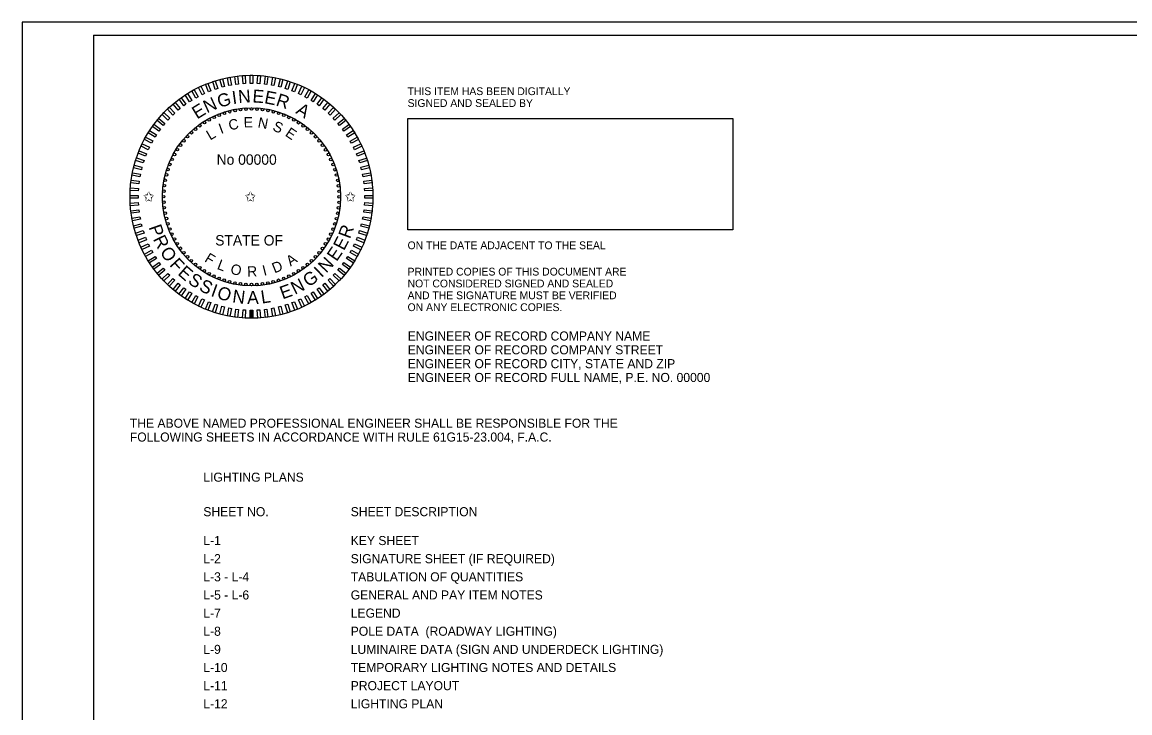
# Model space of a CAD drawing. Extents: x -830008.4 to -829991.9, y 1290284.1 to 1290294.7.
# Drawn here: x -830008.37 to -829999.82, y 1290289.35 to 1290294.68 of the extents above; entities that cross this region are included whole.
import ezdxf

# ---------------------------------------------------------------- set-up
doc = ezdxf.new("R2010")
doc.units = 0
for name, color, linetype in [('LeaderLine_dp', 7, 'Continuous'), ('Logo_dp', 7, 'Continuous'), ('NonPlottingEle_dp', 7, 'Continuous'), ('PlotBorder_dp', 7, 'Continuous'), ('SheetBorder_dp', 7, 'Continuous'), ('TextNotes', 7, 'Continuous')]:
    doc.layers.add(name, color=color, linetype=linetype)

msp = doc.modelspace()

# ---------------------------------------------------------------- linework, layer by layer
at = {"layer": 'Logo_dp'}
for p, q in [((-830006.6142, 1290292.3927), (-830006.6144, 1290292.4552)), ((-830006.6042, 1290292.3927), (-830006.6044, 1290292.4552)), ((-830006.5942, 1290292.3927), (-830006.5944, 1290292.4552))]:
    msp.add_line(p, q, dxfattribs=at)
for points in [[(-830006.8119, 1290294.1803), (-830006.8315, 1290294.1753), (-830006.847, 1290294.2357), (-830006.8275, 1290294.2408)], [(-830006.7581, 1290294.1916), (-830006.778, 1290294.1879), (-830006.7897, 1290294.2492), (-830006.7698, 1290294.253)], [(-830006.7037, 1290294.1996), (-830006.7238, 1290294.1971), (-830006.7316, 1290294.259), (-830006.7116, 1290294.2616)], [(-830006.649, 1290294.2042), (-830006.6691, 1290294.2029), (-830006.673, 1290294.2652), (-830006.6529, 1290294.2665)], [(-830006.594, 1290294.2052), (-830006.6142, 1290294.2052), (-830006.6142, 1290294.2677), (-830006.594, 1290294.2677)], [(-830006.5391, 1290294.2029), (-830006.5592, 1290294.2041), (-830006.5553, 1290294.2665), (-830006.5352, 1290294.2652)], [(-830006.4844, 1290294.1971), (-830006.5044, 1290294.1996), (-830006.4966, 1290294.2615), (-830006.4766, 1290294.259)], [(-830006.4302, 1290294.1878), (-830006.45, 1290294.1916), (-830006.4383, 1290294.2529), (-830006.4185, 1290294.2492)], [(-830006.3767, 1290294.1752), (-830006.3963, 1290294.1802), (-830006.3807, 1290294.2407), (-830006.3612, 1290294.2357)], [(-830007.0168, 1290294.1019), (-830007.0345, 1290294.0922), (-830007.0646, 1290294.1469), (-830007.0469, 1290294.1566)], [(-830006.9675, 1290294.1263), (-830006.9858, 1290294.1177), (-830007.0124, 1290294.1742), (-830006.9941, 1290294.1828)], [(-830006.9168, 1290294.1475), (-830006.9356, 1290294.1401), (-830006.9586, 1290294.1982), (-830006.9398, 1290294.2056)], [(-830006.8649, 1290294.1656), (-830006.8841, 1290294.1593), (-830006.9034, 1290294.2187), (-830006.8842, 1290294.2249)], [(-830006.3241, 1290294.1593), (-830006.3433, 1290294.1655), (-830006.324, 1290294.2249), (-830006.3048, 1290294.2186)], [(-830006.2726, 1290294.14), (-830006.2914, 1290294.1475), (-830006.2684, 1290294.2055), (-830006.2496, 1290294.1981)], [(-830006.2224, 1290294.1176), (-830006.2407, 1290294.1262), (-830006.2141, 1290294.1827), (-830006.1958, 1290294.1741)], [(-830006.1737, 1290294.0921), (-830006.1914, 1290294.1018), (-830006.1613, 1290294.1565), (-830006.1436, 1290294.1468)], [(-830007.1541, 1290294.0109), (-830007.1697, 1290293.9981), (-830007.2095, 1290294.0462), (-830007.1939, 1290294.059)], [(-830007.1103, 1290294.0441), (-830007.1266, 1290294.0322), (-830007.1633, 1290294.0828), (-830007.147, 1290294.0946)], [(-830007.0644, 1290294.0745), (-830007.0815, 1290294.0637), (-830007.1149, 1290294.1164), (-830007.0979, 1290294.1272)], [(-830006.1267, 1290294.0636), (-830006.1438, 1290294.0744), (-830006.1103, 1290294.1271), (-830006.0933, 1290294.1163)], [(-830006.0816, 1290294.0321), (-830006.0979, 1290294.044), (-830006.0612, 1290294.0945), (-830006.0449, 1290294.0827)], [(-830006.0386, 1290293.9979), (-830006.0541, 1290294.0108), (-830006.0143, 1290294.0589), (-830005.9988, 1290294.046)], [(-830007.2351, 1290293.9366), (-830007.2489, 1290293.9219), (-830007.2944, 1290293.9647), (-830007.2806, 1290293.9794)], [(-830007.1958, 1290293.9751), (-830007.2105, 1290293.9612), (-830007.2532, 1290294.0067), (-830007.2385, 1290294.0206)], [(-830005.9978, 1290293.9611), (-830006.0125, 1290293.9749), (-830005.9697, 1290294.0204), (-830005.955, 1290294.0066)], [(-830005.9593, 1290293.9218), (-830005.9732, 1290293.9365), (-830005.9276, 1290293.9792), (-830005.9138, 1290293.9645)], [(-830007.3061, 1290293.8528), (-830007.318, 1290293.8364), (-830007.3685, 1290293.8731), (-830007.3566, 1290293.8895)], [(-830007.2719, 1290293.8958), (-830007.2848, 1290293.8803), (-830007.3329, 1290293.9201), (-830007.32, 1290293.9356)], [(-830005.9235, 1290293.8801), (-830005.9363, 1290293.8957), (-830005.8882, 1290293.9355), (-830005.8754, 1290293.9199)], [(-830005.8903, 1290293.8363), (-830005.9021, 1290293.8526), (-830005.8516, 1290293.8893), (-830005.8398, 1290293.873)], [(-830007.3375, 1290293.8077), (-830007.3484, 1290293.7906), (-830007.4011, 1290293.8241), (-830007.3903, 1290293.8411)], [(-830005.8599, 1290293.7905), (-830005.8707, 1290293.8075), (-830005.818, 1290293.841), (-830005.8072, 1290293.8239)], [(-830007.3916, 1290293.712), (-830007.4002, 1290293.6937), (-830007.4567, 1290293.7203), (-830007.4481, 1290293.7386)], [(-830007.3661, 1290293.7607), (-830007.3758, 1290293.743), (-830007.4305, 1290293.7731), (-830007.4208, 1290293.7908)], [(-830005.8325, 1290293.7428), (-830005.8422, 1290293.7605), (-830005.7875, 1290293.7906), (-830005.7778, 1290293.7729)], [(-830005.8081, 1290293.6936), (-830005.8167, 1290293.7118), (-830005.7602, 1290293.7384), (-830005.7516, 1290293.7201)], [(-830007.414, 1290293.6618), (-830007.4214, 1290293.643), (-830007.4795, 1290293.666), (-830007.4721, 1290293.6848)], [(-830005.7868, 1290293.6429), (-830005.7943, 1290293.6616), (-830005.7362, 1290293.6846), (-830005.7288, 1290293.6658)], [(-830007.4492, 1290293.5577), (-830007.4542, 1290293.5381), (-830007.5147, 1290293.5537), (-830007.5097, 1290293.5732)], [(-830007.4332, 1290293.6103), (-830007.4395, 1290293.5911), (-830007.4989, 1290293.6104), (-830007.4926, 1290293.6296)], [(-830005.7688, 1290293.5909), (-830005.7751, 1290293.6101), (-830005.7157, 1290293.6294), (-830005.7094, 1290293.6102)], [(-830005.7541, 1290293.538), (-830005.7591, 1290293.5575), (-830005.6987, 1290293.573), (-830005.6936, 1290293.5535)], [(-830007.4618, 1290293.5042), (-830007.4656, 1290293.4843), (-830007.5269, 1290293.496), (-830007.5231, 1290293.5159)], [(-830005.7427, 1290293.4842), (-830005.7465, 1290293.504), (-830005.6852, 1290293.5157), (-830005.6814, 1290293.4959)], [(-830007.4768, 1290293.3953), (-830007.4781, 1290293.3752), (-830007.5404, 1290293.3791), (-830007.5392, 1290293.3992)], [(-830007.471, 1290293.45), (-830007.4736, 1290293.43), (-830007.5355, 1290293.4378), (-830007.533, 1290293.4578)], [(-830005.7348, 1290293.4298), (-830005.7373, 1290293.4498), (-830005.6754, 1290293.4576), (-830005.6728, 1290293.4376)], [(-830005.7302, 1290293.375), (-830005.7315, 1290293.3951), (-830005.6692, 1290293.3991), (-830005.6679, 1290293.3789)], [(-830007.4792, 1290293.3404), (-830007.4792, 1290293.3202), (-830007.5417, 1290293.3202), (-830007.5417, 1290293.3404)], [(-830005.7292, 1290293.32), (-830005.7292, 1290293.3402), (-830005.6667, 1290293.3402), (-830005.6667, 1290293.32)], [(-830007.4781, 1290293.2854), (-830007.4769, 1290293.2653), (-830007.5392, 1290293.2614), (-830007.5404, 1290293.2815)], [(-830007.4736, 1290293.2306), (-830007.4711, 1290293.2106), (-830007.533, 1290293.2028), (-830007.5355, 1290293.2228)], [(-830005.7373, 1290293.2104), (-830005.7348, 1290293.2305), (-830005.6729, 1290293.2226), (-830005.6754, 1290293.2026)], [(-830005.7315, 1290293.2651), (-830005.7303, 1290293.2852), (-830005.6679, 1290293.2813), (-830005.6692, 1290293.2612)], [(-830007.4656, 1290293.1762), (-830007.4618, 1290293.1564), (-830007.5232, 1290293.1447), (-830007.527, 1290293.1645)], [(-830007.4543, 1290293.1225), (-830007.4492, 1290293.1029), (-830007.5097, 1290293.0874), (-830007.5147, 1290293.1069)], [(-830005.7592, 1290293.1027), (-830005.7542, 1290293.1223), (-830005.6937, 1290293.1068), (-830005.6987, 1290293.0872)], [(-830005.7466, 1290293.1562), (-830005.7428, 1290293.1761), (-830005.6814, 1290293.1644), (-830005.6852, 1290293.1445)], [(-830007.4395, 1290293.0695), (-830007.4333, 1290293.0503), (-830007.4927, 1290293.031), (-830007.4989, 1290293.0502)], [(-830005.7751, 1290293.0501), (-830005.7689, 1290293.0693), (-830005.7095, 1290293.05), (-830005.7157, 1290293.0308)], [(-830007.4215, 1290293.0176), (-830007.4141, 1290292.9988), (-830007.4721, 1290292.9758), (-830007.4796, 1290292.9946)], [(-830007.4003, 1290292.9669), (-830007.3917, 1290292.9486), (-830007.4482, 1290292.922), (-830007.4568, 1290292.9403)], [(-830005.8168, 1290292.9484), (-830005.8082, 1290292.9667), (-830005.7517, 1290292.9401), (-830005.7603, 1290292.9218)], [(-830005.7943, 1290292.9986), (-830005.7869, 1290293.0174), (-830005.7289, 1290292.9944), (-830005.7363, 1290292.9756)], [(-830007.3759, 1290292.9176), (-830007.3662, 1290292.8999), (-830007.4209, 1290292.8698), (-830007.4306, 1290292.8875)], [(-830007.3485, 1290292.8699), (-830007.3376, 1290292.8529), (-830007.3904, 1290292.8194), (-830007.4012, 1290292.8365)], [(-830005.8708, 1290292.8527), (-830005.86, 1290292.8698), (-830005.8073, 1290292.8363), (-830005.8181, 1290292.8193)], [(-830005.8423, 1290292.8997), (-830005.8326, 1290292.9174), (-830005.7779, 1290292.8873), (-830005.7876, 1290292.8697)], [(-830007.3181, 1290292.8241), (-830007.3062, 1290292.8078), (-830007.3567, 1290292.7711), (-830007.3686, 1290292.7874)], [(-830007.2849, 1290292.7803), (-830007.272, 1290292.7647), (-830007.3201, 1290292.7249), (-830007.333, 1290292.7405)], [(-830005.9365, 1290292.7646), (-830005.9236, 1290292.7801), (-830005.8755, 1290292.7403), (-830005.8883, 1290292.7248)], [(-830005.9023, 1290292.8076), (-830005.8904, 1290292.824), (-830005.8399, 1290292.7873), (-830005.8517, 1290292.7709)], [(-830007.249, 1290292.7386), (-830007.2352, 1290292.7239), (-830007.2807, 1290292.6812), (-830007.2945, 1290292.6959)], [(-830007.2106, 1290292.6993), (-830007.1959, 1290292.6855), (-830007.2386, 1290292.64), (-830007.2533, 1290292.6538)], [(-830006.0126, 1290292.6854), (-830005.9979, 1290292.6992), (-830005.9551, 1290292.6537), (-830005.9699, 1290292.6398)], [(-830005.9733, 1290292.7238), (-830005.9595, 1290292.7385), (-830005.9139, 1290292.6958), (-830005.9278, 1290292.681)], [(-830007.1698, 1290292.6625), (-830007.1542, 1290292.6496), (-830007.194, 1290292.6015), (-830007.2096, 1290292.6144)], [(-830007.1268, 1290292.6283), (-830007.1104, 1290292.6164), (-830007.1471, 1290292.5659), (-830007.1635, 1290292.5778)], [(-830006.0981, 1290292.6163), (-830006.0818, 1290292.6282), (-830006.0451, 1290292.5777), (-830006.0614, 1290292.5658)], [(-830006.0543, 1290292.6495), (-830006.0387, 1290292.6624), (-830005.9989, 1290292.6142), (-830006.0145, 1290292.6014)], [(-830007.0816, 1290292.5969), (-830007.0646, 1290292.586), (-830007.0981, 1290292.5333), (-830007.1151, 1290292.5441)], [(-830007.0347, 1290292.5683), (-830007.017, 1290292.5586), (-830007.047, 1290292.5039), (-830007.0647, 1290292.5136)], [(-830006.986, 1290292.5428), (-830006.9677, 1290292.5342), (-830006.9943, 1290292.4777), (-830007.0126, 1290292.4863)], [(-830006.9358, 1290292.5204), (-830006.917, 1290292.5129), (-830006.94, 1290292.4549), (-830006.9588, 1290292.4623)], [(-830006.2915, 1290292.5129), (-830006.2728, 1290292.5203), (-830006.2498, 1290292.4623), (-830006.2685, 1290292.4548)], [(-830006.2408, 1290292.5341), (-830006.2226, 1290292.5427), (-830006.196, 1290292.4862), (-830006.2142, 1290292.4776)], [(-830006.1916, 1290292.5585), (-830006.1739, 1290292.5682), (-830006.1438, 1290292.5135), (-830006.1615, 1290292.5038)], [(-830006.1439, 1290292.5859), (-830006.1269, 1290292.5968), (-830006.0934, 1290292.544), (-830006.1105, 1290292.5332)], [(-830006.8843, 1290292.5012), (-830006.8651, 1290292.4949), (-830006.8844, 1290292.4355), (-830006.9036, 1290292.4418)], [(-830006.8317, 1290292.4852), (-830006.8121, 1290292.4802), (-830006.8276, 1290292.4197), (-830006.8472, 1290292.4247)], [(-830006.7782, 1290292.4726), (-830006.7583, 1290292.4688), (-830006.77, 1290292.4075), (-830006.7899, 1290292.4113)], [(-830006.724, 1290292.4634), (-830006.7039, 1290292.4608), (-830006.7118, 1290292.3989), (-830006.7318, 1290292.4014)], [(-830006.6693, 1290292.4575), (-830006.6491, 1290292.4563), (-830006.6531, 1290292.394), (-830006.6732, 1290292.3952)], [(-830006.6144, 1290292.4552), (-830006.5942, 1290292.4552), (-830006.5942, 1290292.3927), (-830006.6144, 1290292.3927)], [(-830006.5594, 1290292.4563), (-830006.5393, 1290292.4575), (-830006.5353, 1290292.3952), (-830006.5555, 1290292.3939)], [(-830006.5046, 1290292.4608), (-830006.4846, 1290292.4633), (-830006.4768, 1290292.4014), (-830006.4968, 1290292.3989)], [(-830006.4502, 1290292.4688), (-830006.4304, 1290292.4726), (-830006.4187, 1290292.4112), (-830006.4385, 1290292.4074)], [(-830006.3964, 1290292.4801), (-830006.3769, 1290292.4852), (-830006.3614, 1290292.4247), (-830006.3809, 1290292.4197)], [(-830006.3435, 1290292.4949), (-830006.3243, 1290292.5011), (-830006.305, 1290292.4417), (-830006.3242, 1290292.4355)]]:
    msp.add_lwpolyline(points, close=True, dxfattribs=at)
for centre in [(-830006.813, 1290293.9747), (-830006.7721, 1290293.9865), (-830006.7306, 1290293.9958), (-830006.6885, 1290294.0024), (-830006.6462, 1290294.0064), (-830006.6036, 1290294.0077), (-830006.5611, 1290294.0063), (-830006.5187, 1290294.0023), (-830006.4767, 1290293.9956), (-830006.4352, 1290293.9863), (-830006.3943, 1290293.9743), (-830007.0019, 1290293.8786), (-830006.9667, 1290293.9025), (-830006.9301, 1290293.9241), (-830006.8921, 1290293.9434), (-830006.8531, 1290293.9603), (-830006.3543, 1290293.9599), (-830006.3152, 1290293.943), (-830006.2773, 1290293.9236), (-830006.2407, 1290293.9019), (-830006.2055, 1290293.878), (-830007.0976, 1290293.7944), (-830007.0675, 1290293.8244), (-830007.0356, 1290293.8526), (-830006.1719, 1290293.8518), (-830006.14, 1290293.8237), (-830006.1099, 1290293.7936), (-830007.1519, 1290293.7289), (-830007.1258, 1290293.7625), (-830006.0818, 1290293.7616), (-830006.0558, 1290293.728), (-830007.1976, 1290293.6571), (-830007.1759, 1290293.6937), (-830006.0319, 1290293.6927), (-830006.0102, 1290293.6561), (-830007.2483, 1290293.5401), (-830007.2339, 1290293.5801), (-830007.2169, 1290293.6192), (-830005.9909, 1290293.6181), (-830005.9741, 1290293.5791), (-830005.9597, 1290293.539), (-830007.2695, 1290293.4577), (-830007.2602, 1290293.4992), (-830005.9479, 1290293.4981), (-830005.9386, 1290293.4566), (-830007.2803, 1290293.3733), (-830007.2762, 1290293.4157), (-830005.932, 1290293.4146), (-830005.928, 1290293.3722), (-830007.2816, 1290293.3308), (-830007.2803, 1290293.2882), (-830005.9281, 1290293.2871), (-830005.9267, 1290293.3296), (-830007.2764, 1290293.2459), (-830007.2698, 1290293.2038), (-830005.9388, 1290293.2027), (-830005.9321, 1290293.2447), (-830007.2605, 1290293.1623), (-830007.2487, 1290293.1214), (-830005.96, 1290293.1203), (-830005.9481, 1290293.1612), (-830007.2343, 1290293.0813), (-830007.2174, 1290293.0423), (-830005.9914, 1290293.0412), (-830005.9745, 1290293.0803), (-830007.1981, 1290293.0043), (-830007.1765, 1290292.9677), (-830006.0325, 1290292.9667), (-830006.0108, 1290293.0033), (-830007.1526, 1290292.9325), (-830007.1265, 1290292.8988), (-830007.0984, 1290292.8669), (-830006.1107, 1290292.866), (-830006.0825, 1290292.8979), (-830006.0564, 1290292.9315), (-830007.0684, 1290292.8367), (-830007.0365, 1290292.8086), (-830007.0028, 1290292.7825), (-830006.2064, 1290292.7818), (-830006.1728, 1290292.8079), (-830006.1408, 1290292.836), (-830006.9677, 1290292.7585), (-830006.931, 1290292.7368), (-830006.8931, 1290292.7175), (-830006.8541, 1290292.7005), (-830006.8141, 1290292.6861), (-830006.3954, 1290292.6857), (-830006.3553, 1290292.7001), (-830006.3162, 1290292.717), (-830006.2783, 1290292.7363), (-830006.2417, 1290292.7579), (-830006.7732, 1290292.6742), (-830006.7317, 1290292.6648), (-830006.6897, 1290292.6582), (-830006.6473, 1290292.6541), (-830006.6042, 1290292.6527), (-830006.5622, 1290292.654), (-830006.5198, 1290292.658), (-830006.4778, 1290292.6646), (-830006.4362, 1290292.6739)]:
    msp.add_circle(centre, 0.01, dxfattribs=at)
at = {"layer": 'NonPlottingEle_dp'}
msp.add_lwpolyline([(-830005.3978, 1290293.9343), (-830002.8886, 1290293.9343), (-830002.8886, 1290293.0739), (-830005.3978, 1290293.0739)], close=True, dxfattribs=at)
for radius in [0.9375, 0.6875]:
    msp.add_circle((-830006.6042, 1290293.3302), radius, dxfattribs=at)
at = {"layer": 'PlotBorder_dp'}
msp.add_lwpolyline([(-830008.3742, 1290284.078), (-829991.8742, 1290284.078), (-829991.8742, 1290294.678), (-830008.3742, 1290294.678)], close=True, dxfattribs=at)
at = {"layer": 'SheetBorder_dp'}
for q in [(-830007.8242, 1290284.178), (-829992.4242, 1290294.578)]:
    msp.add_line((-830007.8242, 1290294.578), q, dxfattribs=at)

# ---------------------------------------------------------------- texts
at = {"layer": 'LeaderLine_dp'}
for s, p in [('THE ABOVE NAMED PROFESSIONAL ENGINEER SHALL BE RESPONSIBLE FOR THE', (-830007.5429, 1290291.5474)), ('FOLLOWING SHEETS IN ACCORDANCE WITH RULE 61G15-23.004, F.A.C.', (-830007.5429, 1290291.4406))]:
    msp.add_text(s, height=0.07, dxfattribs=at).set_placement(p)
at = {"layer": 'Logo_dp'}
for s, height, rotation, p in [('I', 0.1, 7.83343, (-830006.7476, 1290294.0448)), ('N', 0.1, 4.30023, (-830006.7033, 1290294.0523)), ('E', 0.1, 356.05007, (-830006.5987, 1290294.0591)), ('E', 0.1, 349.00783, (-830006.5094, 1290294.0529)), ('N', 0.1, 24.61763, (-830006.9479, 1290293.973)), ('G', 0.1, 16.36746, (-830006.8521, 1290294.0156)), ('R', 0.1, 341.96559, (-830006.4215, 1290294.0358)), ('E', 0.1, 31.65987, (-830007.0241, 1290293.926)), ('A', 0.1, 329.06489, (-830006.2685, 1290293.9772)), ('I', 0.08, 20.01168, (-830006.8399, 1290293.8143)), ('C', 0.08, 12.20255, (-830006.7719, 1290293.8418)), ('E', 0.08, 0.41861, (-830006.6639, 1290293.8653)), ('N', 0.08, 349.29143, (-830006.5595, 1290293.8668)), ('S', 0.08, 337.02207, (-830006.4465, 1290293.845)), ('L', 0.08, 30.40215, (-830006.9233, 1290293.7638)), ('E', 0.08, 325.86633, (-830006.3499, 1290293.8048)), ('P', 0.1, 289.40551, (-830007.3989, 1290293.0956)), ('R', 0.1, 296.14576, (-830007.3659, 1290293.004)), ('R', 0.1, 69.5134, (-830005.844, 1290293.0005)), ('E', 0.1, 55.42892, (-830005.9471, 1290292.8254)), ('E', 0.1, 62.47116, (-830005.8902, 1290292.9098)), ('O', 0.1, 303.96711, (-830007.3144, 1290292.9034)), ('F', 0.08, 328.72408, (-830006.9722, 1290292.8336)), ('A', 0.08, 34.49917, (-830006.3023, 1290292.7908)), ('N', 0.1, 47.17876, (-830006.0263, 1290292.7364)), ('F', 0.1, 312.62798, (-830007.242, 1290292.8013)), ('E', 0.1, 319.07833, (-830007.1785, 1290292.733)), ('L', 0.08, 339.29159, (-830006.8749, 1290292.7745)), ('O', 0.08, 349.68206, (-830006.7703, 1290292.7348)), ('R', 0.08, 2.33977, (-830006.6358, 1290292.7129)), ('I', 0.08, 14.20366, (-830006.5082, 1290292.7196)), ('D', 0.08, 22.01279, (-830006.4261, 1290292.7383)), ('I', 0.1, 43.64556, (-830006.064, 1290292.7019)), ('S', 0.1, 326.12056, (-830007.101, 1290292.6671)), ('N', 0.1, 26.86136, (-830006.2685, 1290292.5727)), ('G', 0.1, 35.11153, (-830006.1632, 1290292.6287)), ('S', 0.1, 333.193, (-830007.0156, 1290292.6109)), ('I', 0.1, 340.26543, (-830006.9239, 1290292.5658)), ('O', 0.1, 343.79863, (-830006.8762, 1290292.5475)), ('N', 0.1, 352.45949, (-830006.7552, 1290292.5155)), ('L', 0.1, 8.47665, (-830006.5245, 1290292.5054)), ('E', 0.1, 19.81912, (-830006.3639, 1290292.5372)), ('A', 0.1, 0.70966, (-830006.6367, 1290292.5022))]:
    msp.add_text(s, height=height, rotation=rotation, dxfattribs=at).set_placement(p)
for s, p in [('No 00000', (-830006.8731, 1290293.5774)), ('✩', (-830007.4391, 1290293.2923)), ('✩', (-830006.6544, 1290293.2923)), ('✩', (-830005.8826, 1290293.2923)), ('STATE OF', (-830006.8839, 1290292.954))]:
    msp.add_text(s, height=0.08, dxfattribs=at).set_placement(p)
at = {"layer": 'TextNotes'}
for s, height, p in [('THIS ITEM HAS BEEN DIGITALLY', 0.06, (-830005.399, 1290294.115)), ('SIGNED AND SEALED BY', 0.06, (-830005.399, 1290294.0235)), ('ON THE DATE ADJACENT TO THE SEAL', 0.06, (-830005.399, 1290292.9255)), ('PRINTED COPIES OF THIS DOCUMENT ARE', 0.06, (-830005.399, 1290292.7223)), ('NOT CONSIDERED SIGNED AND SEALED', 0.06, (-830005.399, 1290292.6308)), ('AND THE SIGNATURE MUST BE VERIFIED', 0.06, (-830005.399, 1290292.5393)), ('ON ANY ELECTRONIC COPIES.', 0.06, (-830005.399, 1290292.4478)), ('ENGINEER OF RECORD COMPANY NAME', 0.07, (-830005.3978, 1290292.2206)), ('ENGINEER OF RECORD COMPANY STREET', 0.07, (-830005.3978, 1290292.1139)), ('ENGINEER OF RECORD CITY, STATE AND ZIP', 0.07, (-830005.3978, 1290292.0071)), ('ENGINEER OF RECORD FULL NAME, P.E. NO. 00000', 0.07, (-830005.3978, 1290291.9004)), ('LIGHTING PLANS', 0.07, (-830006.9758, 1290291.1307)), ('SHEET NO.', 0.07, (-830006.9758, 1290290.8644)), ('SHEET DESCRIPTION', 0.07, (-830005.838, 1290290.8644)), ('L-1', 0.07, (-830006.9758, 1290290.6416)), ('KEY SHEET', 0.07, (-830005.838, 1290290.6416)), ('L-2 ', 0.07, (-830006.9758, 1290290.5016)), ('SIGNATURE SHEET (IF REQUIRED)', 0.07, (-830005.838, 1290290.5016)), ('L-3 - L-4', 0.07, (-830006.9758, 1290290.3616)), ('TABULATION OF QUANTITIES', 0.07, (-830005.838, 1290290.3616)), ('L-5 - L-6', 0.07, (-830006.9758, 1290290.2216)), ('GENERAL AND PAY ITEM NOTES', 0.07, (-830005.838, 1290290.2216)), ('L-7 ', 0.07, (-830006.9758, 1290290.0816)), ('LEGEND', 0.07, (-830005.838, 1290290.0816)), ('L-8', 0.07, (-830006.9758, 1290289.9416)), ('POLE DATA  (ROADWAY LIGHTING)', 0.07, (-830005.838, 1290289.9416)), ('L-9', 0.07, (-830006.9758, 1290289.8016)), ('LUMINAIRE DATA (SIGN AND UNDERDECK LIGHTING)', 0.07, (-830005.838, 1290289.8016)), ('L-10', 0.07, (-830006.9758, 1290289.6616)), ('TEMPORARY LIGHTING NOTES AND DETAILS', 0.07, (-830005.838, 1290289.6616)), ('L-11', 0.07, (-830006.9758, 1290289.5216)), ('PROJECT LAYOUT', 0.07, (-830005.838, 1290289.5216)), ('L-12', 0.07, (-830006.9758, 1290289.3816)), ('LIGHTING PLAN', 0.07, (-830005.838, 1290289.3816))]:
    msp.add_text(s, height=height, dxfattribs=at).set_placement(p)

doc.saveas('drawing.dxf')
